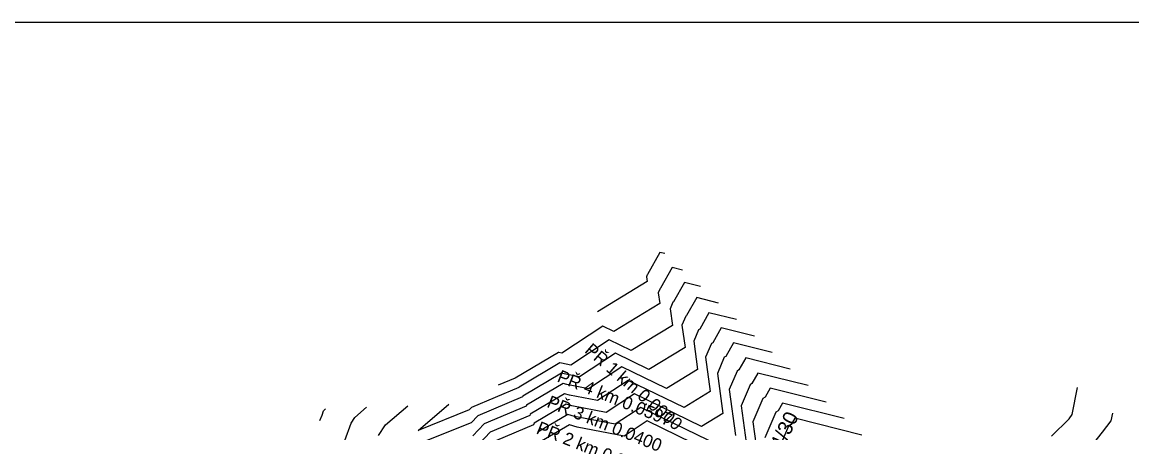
# Model space of a CAD drawing. Extents: x -549394 to -546608, y -1037055 to -1033629.
# Drawn here: x -548997 to -548203, y -1033923 to -1033629 of the extents above; entities that cross this region are included whole.
import ezdxf

# ---------------------------------------------------------------- set-up
doc = ezdxf.new("R2010")
doc.units = 0
for name, color, linetype in [('HLAVNI_VRST', 7, 'Continuous'), ('NORM_VRST', 7, 'Continuous'), ('RAM', 7, 'Continuous'), ('x_popis_pricne_rezy_C21a', 7, 'Continuous'), ('x_popis_velky_C21a', 7, 'Continuous')]:
    doc.layers.add(name, color=color, linetype=linetype)

msp = doc.modelspace()

# ---------------------------------------------------------------- linework, layer by layer
at = {"layer": 'HLAVNI_VRST'}
for p, q in [((-548522.906783, -1033815.458484), (-548530.682041, -1033829.276571)), ((-548511.357757, -1033818.35895), (-548522.906783, -1033815.458484)), ((-548531.134262, -1033829.547053), (-548533.168149, -1033834.323377)), ((-548533.168149, -1033834.323377), (-548531.541471, -1033846.109067)), ((-548530.682041, -1033829.276571), (-548531.134262, -1033829.547053)), ((-548531.541471, -1033846.109067), (-548560.907616, -1033864.145814)), ((-548576.79263, -1033856.415015), (-548604.233988, -1033874.451349)), ((-548560.907616, -1033864.145814), (-548576.79263, -1033856.415015)), ((-548611.939935, -1033872.853694), (-548641.224211, -1033890.237709)), ((-548610.833285, -1033873.186438), (-548611.939935, -1033872.853694)), ((-548604.233988, -1033874.451349), (-548610.833285, -1033873.186438)), ((-548479.080696, -1033869.399478), (-548483.924107, -1033878.007125)), ((-548447.198879, -1033877.406398), (-548479.080696, -1033869.399478)), ((-548485.180991, -1033878.758891), (-548490.833895, -1033892.034012)), ((-548483.924107, -1033878.007125), (-548485.180991, -1033878.758891)), ((-548641.340498, -1033890.549585), (-548675.250909, -1033904.816883)), ((-548641.224211, -1033890.237709), (-548641.340498, -1033890.549585)), ((-548245.403377, -1033909.901364), (-548241.646026, -1033890.466474)), ((-548490.833895, -1033892.034012), (-548486.312771, -1033924.790682)), ((-548713.352941, -1033921.245882), (-548691.502983, -1033902.502431)), ((-548676.797447, -1033906.449787), (-548713.352941, -1033921.245882)), ((-548675.250909, -1033904.816883), (-548676.797447, -1033906.449787)), ((-548554.071999, -1033904.761011), (-548572.444831, -1033916.836892)), ((-548498.073314, -1033932.014031), (-548554.071999, -1033904.761011)), ((-548606.361485, -1033909.805035), (-548627.803158, -1033922.533449)), ((-548601.490715, -1033911.269562), (-548606.361485, -1033909.805035)), ((-548572.444831, -1033916.836892), (-548601.490715, -1033911.269562)), ((-548260.394045, -1033925.450674), (-548247.64875, -1033912.85875)), ((-548247.64875, -1033912.85875), (-548245.403377, -1033909.901364)), ((-548627.803158, -1033922.533449), (-548628.373693, -1033924.063589))]:
    msp.add_line(p, q, dxfattribs=at)
at = {"layer": 'NORM_VRST'}
for p, q in [((-548540.437217, -1033793.882087), (-548549.385215, -1033809.78435)), ((-548537.021308, -1033794.739971), (-548540.437217, -1033793.882087)), ((-548549.51557, -1033809.862318), (-548550.101851, -1033811.239123)), ((-548550.101851, -1033811.239123), (-548549.632951, -1033814.636422)), ((-548549.385215, -1033809.78435), (-548549.51557, -1033809.862318)), ((-548531.672, -1033804.670286), (-548540.033628, -1033819.53046)), ((-548524.189533, -1033806.549461), (-548531.672, -1033804.670286)), ((-548549.632951, -1033814.636422), (-548585.095301, -1033836.41747)), ((-548540.324916, -1033819.704685), (-548541.635, -1033822.78125)), ((-548541.635, -1033822.78125), (-548540.587211, -1033830.372744)), ((-548540.033628, -1033819.53046), (-548540.324916, -1033819.704685)), ((-548514.141565, -1033826.246683), (-548521.330454, -1033839.022682)), ((-548498.525981, -1033830.16844), (-548514.141565, -1033826.246683)), ((-548540.587211, -1033830.372744), (-548573.474477, -1033850.572171)), ((-548521.943607, -1033839.389421), (-548524.701298, -1033845.865504)), ((-548521.330454, -1033839.022682), (-548521.943607, -1033839.389421)), ((-548505.376348, -1033837.034882), (-548511.978867, -1033848.768793)), ((-548485.694206, -1033841.97793), (-548505.376348, -1033837.034882)), ((-548581.336756, -1033846.745815), (-548610.591819, -1033865.974241)), ((-548573.474477, -1033850.572171), (-548581.336756, -1033846.745815)), ((-548524.701298, -1033845.865504), (-548522.495731, -1033861.84539)), ((-548512.752953, -1033849.231788), (-548516.234448, -1033857.407631)), ((-548511.978867, -1033848.768793), (-548512.752953, -1033849.231788)), ((-548496.61113, -1033847.823081), (-548502.627281, -1033858.514904)), ((-548472.86243, -1033853.787419), (-548496.61113, -1033847.823081)), ((-548516.234448, -1033857.407631), (-548513.449991, -1033877.581713)), ((-548503.562299, -1033859.074156), (-548507.767597, -1033868.949758)), ((-548502.627281, -1033858.514904), (-548503.562299, -1033859.074156)), ((-548487.845913, -1033858.61128), (-548493.275694, -1033868.261014)), ((-548460.030654, -1033865.596909), (-548487.845913, -1033858.61128)), ((-548613.055626, -1033865.463426), (-548643.908421, -1033883.778561)), ((-548612.701798, -1033865.569814), (-548613.055626, -1033865.463426)), ((-548610.591819, -1033865.974241), (-548612.701798, -1033865.569814)), ((-548572.248504, -1033866.084214), (-548597.876157, -1033882.928458)), ((-548548.340756, -1033877.719457), (-548572.248504, -1033866.084214)), ((-548522.495731, -1033861.84539), (-548548.340756, -1033877.719457)), ((-548507.767597, -1033868.949758), (-548504.404251, -1033893.318036)), ((-548494.371645, -1033868.916523), (-548499.300746, -1033880.491885)), ((-548493.275694, -1033868.261014), (-548494.371645, -1033868.916523)), ((-548610.824245, -1033880.243962), (-548638.54, -1033896.696857)), ((-548608.964771, -1033880.803063), (-548610.824245, -1033880.243962)), ((-548597.876157, -1033882.928458), (-548608.964771, -1033880.803063)), ((-548567.704378, -1033875.753413), (-548591.518325, -1033891.405566)), ((-548535.773895, -1033891.293101), (-548567.704378, -1033875.753413)), ((-548513.449991, -1033877.581713), (-548535.773895, -1033891.293101)), ((-548499.300746, -1033880.491885), (-548495.358511, -1033909.054359)), ((-548470.315478, -1033880.187677), (-548474.57252, -1033887.753236)), ((-548434.367103, -1033889.215888), (-548470.315478, -1033880.187677)), ((-548643.933859, -1033883.846784), (-548656.119, -1033888.9735)), ((-548643.908421, -1033883.778561), (-548643.933859, -1033883.846784)), ((-548609.708555, -1033887.63423), (-548635.855789, -1033903.156005)), ((-548607.096257, -1033888.419688), (-548609.708555, -1033887.63423)), ((-548591.518325, -1033891.405566), (-548607.096257, -1033888.419688)), ((-548563.160251, -1033885.422613), (-548585.160494, -1033899.882675)), ((-548523.207035, -1033904.866744), (-548563.160251, -1033885.422613)), ((-548475.990336, -1033888.601259), (-548482.367044, -1033903.57614)), ((-548474.57252, -1033887.753236), (-548475.990336, -1033888.601259)), ((-548638.747137, -1033897.252386), (-548670.773636, -1033910.727056)), ((-548638.54, -1033896.696857), (-548638.747137, -1033897.252386)), ((-548608.592865, -1033895.024499), (-548633.171579, -1033909.615153)), ((-548605.227743, -1033896.036312), (-548608.592865, -1033895.024499)), ((-548585.160494, -1033899.882675), (-548605.227743, -1033896.036312)), ((-548558.616125, -1033895.091812), (-548578.802663, -1033908.359783)), ((-548510.640174, -1033918.440388), (-548558.616125, -1033895.091812)), ((-548504.404251, -1033893.318036), (-548523.207035, -1033904.866744)), ((-548466.799682, -1033898.443626), (-548473.900193, -1033915.118267)), ((-548465.220933, -1033897.499347), (-548466.799682, -1033898.443626)), ((-548461.550261, -1033890.975876), (-548465.220933, -1033897.499347)), ((-548421.535327, -1033901.025377), (-548461.550261, -1033890.975876)), ((-548781.018294, -1033907.166143), (-548780.691704, -1033906.664116)), ((-548780.691704, -1033906.664116), (-548779.64663, -1033905.767624)), ((-548758.775305, -1033911.979228), (-548750.265414, -1033904.679227)), ((-548736.858907, -1033917.294341), (-548720.884199, -1033903.590829)), ((-548636.153776, -1033903.955187), (-548666.296364, -1033916.637229)), ((-548635.855789, -1033903.156005), (-548636.153776, -1033903.955187)), ((-548607.477175, -1033902.414767), (-548630.487368, -1033916.074301)), ((-548603.359229, -1033903.652937), (-548607.477175, -1033902.414767)), ((-548578.802663, -1033908.359783), (-548603.359229, -1033903.652937)), ((-548482.367044, -1033903.57614), (-548477.267031, -1033940.527004)), ((-548452.785043, -1033901.764075), (-548455.869347, -1033907.245457)), ((-548408.703551, -1033912.834867), (-548452.785043, -1033901.764075)), ((-548783.762222, -1033914.17), (-548782.183871, -1033910.381935)), ((-548782.183871, -1033910.381935), (-548781.018294, -1033907.166143)), ((-548761.434676, -1033916.067167), (-548758.775305, -1033911.979228)), ((-548670.773636, -1033910.727056), (-548675.542128, -1033915.761844)), ((-548633.560415, -1033910.657988), (-548661.819091, -1033922.547403)), ((-548633.171579, -1033909.615153), (-548633.560415, -1033910.657988)), ((-548549.527873, -1033914.43021), (-548566.087, -1033925.314)), ((-548485.506453, -1033945.587674), (-548549.527873, -1033914.43021)), ((-548495.358511, -1033909.054359), (-548510.640174, -1033918.440388)), ((-548457.609028, -1033908.285994), (-548465.433343, -1033926.660394)), ((-548455.869347, -1033907.245457), (-548457.609028, -1033908.285994)), ((-548444.019826, -1033912.552273), (-548446.51776, -1033916.991568)), ((-548395.871776, -1033924.644357), (-548444.019826, -1033912.552273)), ((-548223.870541, -1033922.623108), (-548217.559221, -1033914.310455)), ((-548217.559221, -1033914.310455), (-548216.505, -1033908.8575)), ((-548770.925806, -1033942.252903), (-548761.434676, -1033916.067167)), ((-548741.851058, -1033924.968191), (-548736.858907, -1033917.294341)), ((-548675.542128, -1033915.761844), (-548711.870673, -1033930.46608)), ((-548666.296364, -1033916.637229), (-548674.286809, -1033925.073901)), ((-548661.819091, -1033922.547403), (-548673.031489, -1033934.385957)), ((-548630.967054, -1033917.360788), (-548657.341818, -1033928.457576)), ((-548630.487368, -1033916.074301), (-548630.967054, -1033917.360788)), ((-548605.245794, -1033917.195303), (-548625.118947, -1033928.992596)), ((-548599.622202, -1033918.886186), (-548605.245794, -1033917.195303)), ((-548566.087, -1033925.314), (-548599.622202, -1033918.886186)), ((-548473.900193, -1033915.118267), (-548468.221291, -1033956.263327)), ((-548448.418374, -1033918.128361), (-548456.966492, -1033938.202521)), ((-548446.51776, -1033916.991568), (-548448.418374, -1033918.128361)), ((-548236.306446, -1033938.183802), (-548223.870541, -1033922.623108))]:
    msp.add_line(p, q, dxfattribs=at)
at = {"layer": 'RAM'}
msp.add_lwpolyline([(-549394.284, -1037054.814), (-549394.284, -1033629.106), (-546608.036, -1033629.106), (-546608.036, -1037054.814), (-549394.284, -1037054.814)], dxfattribs=at)

# ---------------------------------------------------------------- texts
at = {"layer": 'x_popis_pricne_rezy_C21a'}
for s, rotation, p in [('PŘ 1 km 0.0000', 319.079197, (-548594.904093, -1033864.946189)), ('PŘ 4 km 0.0597', 338.101349, (-548614.608048, -1033886.064309)), ('PŘ 3 km 0.0400', 338.101349, (-548621.947956, -1033904.324145)), ('PŘ 2 km 0.0200', 338.101349, (-548629.407275, -1033922.881046))]:
    msp.add_text(s, height=9.06272, rotation=rotation, dxfattribs=at).set_placement(p)
at = {"layer": 'x_popis_velky_C21a'}
msp.add_text('C21a,P4/30', height=10.5, rotation=64.473381, dxfattribs=at).set_placement((-548472.859288, -1033978.068494))

doc.saveas('drawing.dxf')
